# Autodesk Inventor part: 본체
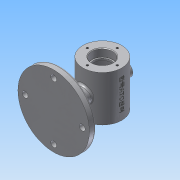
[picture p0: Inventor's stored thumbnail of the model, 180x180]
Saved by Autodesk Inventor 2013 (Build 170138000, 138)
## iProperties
Created: 2018-12
Part Number: 본체
Material: 알루미늄 6061
Document SubType Name: Modeling
Designer: Administrator
Density: 2.71 g/cm^3
Mass: 664.753 g
Surface Area: 551.018 cm^2
Volume: 245.296 cm^3
Author: Administrator
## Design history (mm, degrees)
sketch "스케치2"
  geometry: C1 r 30 at (0, 0); 1 further point
  constraints: 1 centre point, 1 coincident
  dimensions: "d22" = 60 diameter of C1
extrude "돌출2" new body sketch "스케치2" stored distance "d23" = 70; taper "d24" = 0 deg
hole "구멍3" diameter "d27" = 32; stored, may be unused: countersink angle "d31" = 90 deg, drill point angle "d33" = 0 deg; dims "d25" = 10, "d26" = 10, "d28" = 6, "d29" = 4, "d30" = 2, "d32" = 12
hole "구멍4" diameter "d36" = 28; stored, may be unused: countersink angle "d40" = 90 deg, drill point angle "d42" = 0 deg; dims "d34" = 10, "d35" = 10, "d37" = 6, "d38" = 4, "d39" = 2, "d41" = 3
hole "구멍5" diameter "d45" = 50; stored, may be unused: countersink angle "d49" = 90 deg, drill point angle "d51" = 0 deg; dims "d43" = 10, "d44" = 10, "d46" = 6, "d47" = 4, "d48" = 2, "d50" = 40
node "작업 평면1"
sketch "스케치3"
  geometry: C1 r 55 at (0, 0); 1 further point
  constraints: 1 centre point, 1 coincident
  dimensions: "d53" = 110 diameter of C1
extrude "돌출3" join sketch "스케치3" distance "d54" = 10; taper "d55" = 0 deg
sketch "스케치4"
  geometry: L1 (-65, -55)-(-65, 55) reference; L2 (-65, -55)-(-65, 55) reference; L3 (-75, 55)-(-75, -55) reference; L4 (-65, -55)-(-53.478, -12); L5 (-65, 0)-(-53.478, 0); L6 (-53.478, -12)-(-53.478, 0); L7 (-65, 0)-(-65, -55); 1 further point
  constraints: 8 end point, 2 coincident, 2 perpendicular, 1 midpoint
  dimensions: "d56" = 43 vertical distance of L4.start L4.end; "d58" = 165 deg angle of L4 L6
revolve "회전1" sketch "스케치4" stored, may be unused: angle "d59" = 90 deg
sketch "스케치5"
  geometry: C1 r 55 at (0, 0) reference; C2 r 12 at (0, 0) reference; C3 r 12 at (0, 0)
  constraints: 1 centre point, 1 coincident
  dimensions: "d60" = 24 diameter of C3
extrude "돌출4" join sketch "스케치5" stored distance "d61" = 10; taper "d62" = 0 deg
node "작업 평면2"
sketch "스케치6"
  geometry: C1 r 10 at (0, 0); 1 further point
  constraints: 1 centre point, 1 coincident
  dimensions: "d64" = 20 diameter of C1
extrude "돌출5" join sketch "스케치6" stored distance "d65" = 10; taper "d66" = 0 deg
hole "구멍6" diameter "d69" = 10; stored, may be unused: countersink angle "d73" = 90 deg, drill point angle "d75" = 0 deg; dims "d67" = 10, "d68" = 10, "d70" = 6, "d71" = 4, "d72" = 2, "d74" = 40
sketch "스케치7"
  geometry: 1 further point
hole "구멍7" sketch "스케치7" at (0, 44) diameter "d77" = 9; stored, may be unused: countersink angle "d81" = 90 deg, drill point angle "d83" = 0 deg; dims "d78" = 6, "d79" = 4, "d80" = 2, "d82" = 10
hole "구멍8" diameter "d86" = 14; stored, may be unused: countersink angle "d90" = 90 deg, drill point angle "d92" = 0 deg; dims "d84" = 10, "d85" = 10, "d87" = 6, "d88" = 4, "d89" = 2, "d91" = 10
sketch "스케치8"
  geometry: 1 further point
hole "구멍9" sketch "스케치8" at (0, 23) diameter "d97" = 3.242; stored, may be unused: countersink angle "d101" = 90 deg, drill point angle "d103" = 118 deg; dims "d98" = 8, "d99" = 4, "d100" = 2, "d102" = 10
node "작업 평면3"
sketch "스케치9"
  geometry: L1 (30, 35)-(-30, 35) reference; L2 (30, -35)-(30, 35) reference; 2 further points
  constraints: 1 other
  dimensions: "d108" = 35 distance from line of L1 point (0, 0); "d109" = 30 distance from line of L2 point (0, 0)
feature "엠보싱1" sketch "스케치9" dims "d54" = 10, "d55" = 0, "d110" = 0.5, "d111" = 0
fillet "모깎기1" dims "d112" = 3
fillet "모깎기2" dims "d113" = 0.3
chamfer "모따기1" distance "d114" = 1; stored, may be unused: second distance "d115" = 2, angle "d116" = 45 deg
chamfer "모따기2" distance "d117" = 1; stored, may be unused: second distance "d118" = 2, angle "d119" = 45 deg
node "솔리드2"
mirror "대칭1"
pattern_circular "원형 패턴1" dims angle "d94" = 360 deg
pattern_circular "원형 패턴2" dims angle "d105" = 360 deg
mirror "대칭2"
node "투영된 루프1"
node "투영된 루프2"
other parameters: "d52" = -75, "d63" = 37, "d107" = 34.5
